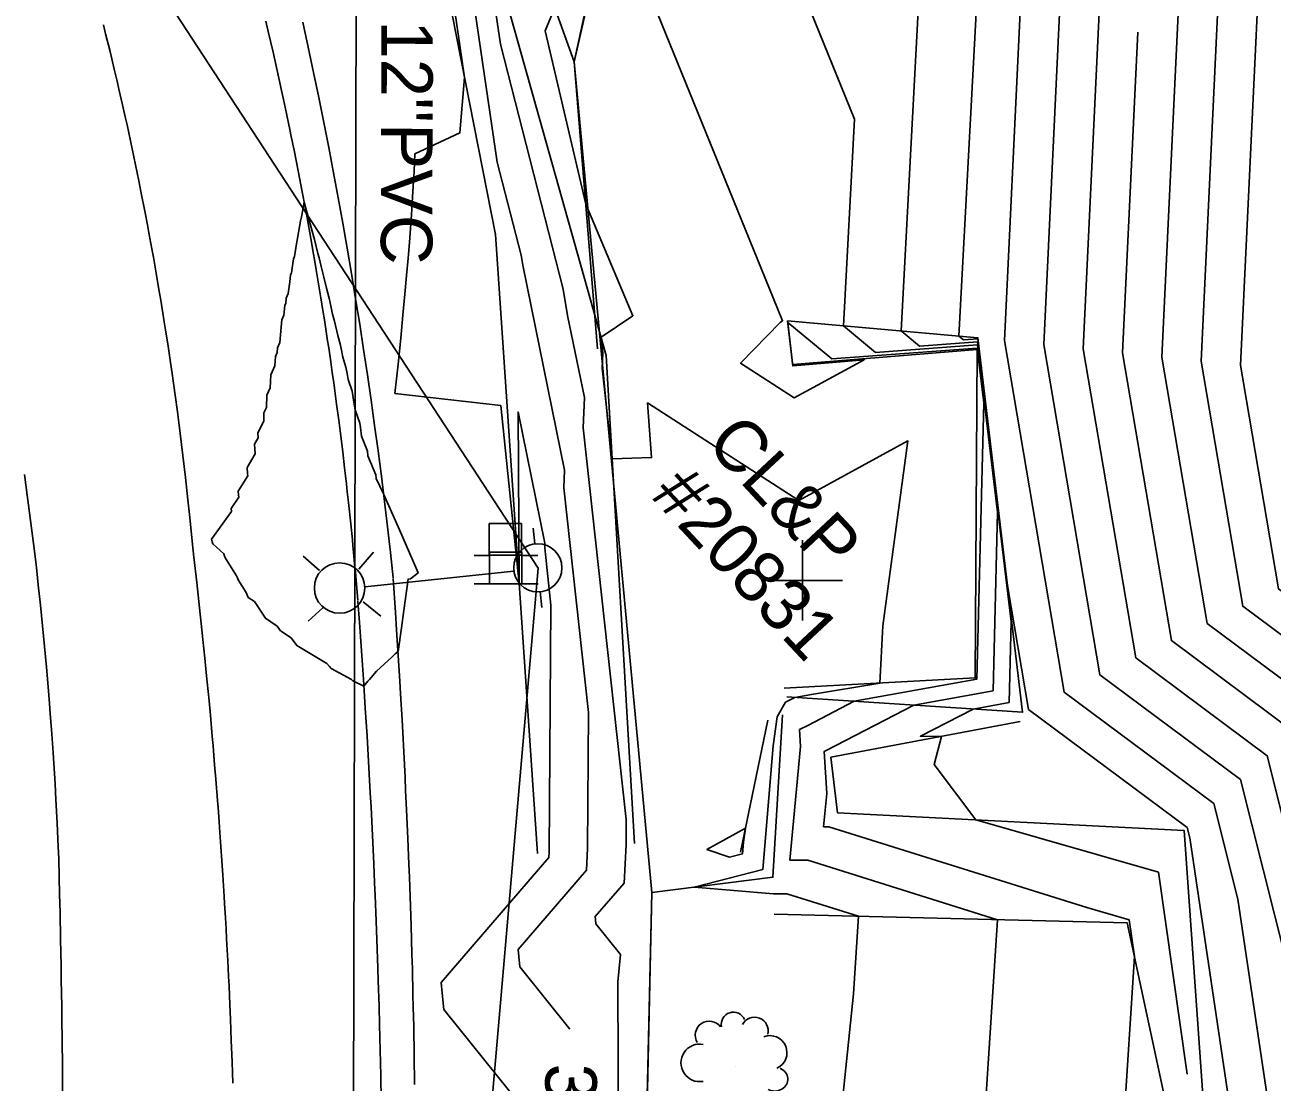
# Model space of a CAD drawing. Extents: x 487096 to 489566, y 221939 to 224454.
# Drawn here: x 488438.1 to 488515.7, y 223406.4 to 223472.1 of the extents above; entities that cross this region are included whole.
import ezdxf

# ---------------------------------------------------------------- set-up
doc = ezdxf.new("R2010")
doc.units = 0
for name, color, linetype in [('SV_BKLN_BKLN', 7, 'Continuous'), ('SV_BKLN_EARTH_TOE', 7, 'Continuous'), ('SV_BKLN_EARTH_TOP', 7, 'Continuous'), ('SV_PIPE_PLAS_12', 7, 'Continuous'), ('SV_PIPE_PLAS_TX', 7, 'Continuous'), ('SV_ROAD_BITRD', 7, 'Continuous'), ('SV_ROWL_HWYLOC', 7, 'Continuous'), ('SV_ROWL_STREET', 7, 'Continuous'), ('SV_SIGN_SIGN', 7, 'Continuous'), ('SV_SURF_INDEX_CONTOUR', 7, 'Continuous'), ('SV_SURF_INTER_CONTOUR', 7, 'Continuous'), ('SV_SURF_SPOT', 7, 'Continuous'), ('SV_TRAF_PVMTL', 7, 'Continuous'), ('SV_TREE_TREEVEG', 7, 'Continuous'), ('SV_UTOH_OVERHEAD_LINES', 7, 'Continuous'), ('SV_UTOH_UPOLT', 7, 'Continuous'), ('SV_UTOH_UTOH_TX', 7, 'Continuous'), ('SV_WALL_STONE_WALL', 7, 'Continuous')]:
    doc.layers.add(name, color=color, linetype=linetype)

msp = doc.modelspace()

# ---------------------------------------------------------------- linework, layer by layer
at = {"layer": 'SV_BKLN_BKLN'}
for points in [[(488485.31, 223430.866), (488497.188, 223431.512), (488497.312, 223451.947), (488485.84, 223451.008)], [(488484.292, 223428.887), (488482.589, 223420.665)]]:
    msp.add_lwpolyline(points, dxfattribs=at)
at = {"layer": 'SV_BKLN_EARTH_TOE'}
for points in [[(488469.961, 223420.582), (488467.339, 223459.105), (488461.972, 223486.415), (488459.949, 223502.528)], [(488484.686, 223416.811), (488506.643, 223416.262), (488512.539, 223388.8)]]:
    msp.add_lwpolyline(points, dxfattribs=at)
at = {"layer": 'SV_BKLN_EARTH_TOP'}
for points in [[(488474.03, 223609.885), (488463.275, 223570.978), (488459.199, 223552.217), (488465.983, 223535.806), (488467.423, 223503.001), (488467.747, 223474.673), (488474.24, 223451.573), (488476.004, 223421.2)], [(488512.539, 223388.8), (488510.187, 223422.021), (488488.627, 223423.114), (488488.217, 223426.57), (488499.994, 223428.804)]]:
    msp.add_lwpolyline(points, dxfattribs=at)
at = {"layer": 'SV_PIPE_PLAS_12'}
msp.add_line((488458.486, 223394.536), (488458.76, 223501.752), dxfattribs=at)
at = {"layer": 'SV_ROAD_BITRD'}
for points in [[(488460.986, 223437.739), (488460.813, 223439.322), (488460.632, 223440.905), (488460.444, 223442.487), (488460.247, 223444.068), (488460.042, 223445.648), (488459.83, 223447.227), (488459.609, 223448.804), (488459.381, 223450.381), (488459.145, 223451.957), (488458.901, 223453.531), (488458.648, 223455.104), (488458.388, 223456.676), (488458.12, 223458.246), (488457.845, 223459.815), (488457.561, 223461.383), (488457.27, 223462.949), (488456.97, 223464.514), (488456.663, 223466.077), (488456.348, 223467.638), (488456.025, 223469.198), (488455.694, 223470.757), (488455.356, 223472.313)], [(488462.314, 223406.214), (488462.289, 223408.014), (488462.257, 223409.813), (488462.233, 223411.013), (488462.214, 223411.813), (488462.174, 223413.413), (488462.149, 223414.313), (488462.095, 223416.112), (488462.034, 223417.912), (488461.99, 223419.112), (488461.959, 223419.912), (488461.893, 223421.511), (488461.814, 223423.311), (488461.758, 223424.511), (488461.72, 223425.311), (488461.639, 223426.91), (488461.575, 223428.11), (488461.531, 223428.91), (488461.441, 223430.51), (488461.394, 223431.309), (488461.297, 223432.909), (488461.196, 223434.509), (488461.126, 223435.575), (488460.982, 223437.708)]]:
    msp.add_lwpolyline(points, dxfattribs=at)
at = {"layer": 'SV_ROWL_HWYLOC'}
msp.add_lwpolyline([(487756.919, 223854.031), (487819.736, 223823.932), (487982.506, 223759.36), (488009.692, 223754.735), (488041.144, 223750.633), (488071.96, 223735.453), (488100.921, 223722.744), (488124.658, 223715.601), (488155.682, 223709.246), (488178.896, 223706.069), (488296.161, 223658.564), (488379.396, 223617.166), (488410.154, 223595.683), (488443.8, 223549.214), (488472.236, 223469.86), (488477.064, 223418.158), (488475.622, 223352.082), (488474.079, 223317.483), (488463.166, 223231.249), (488461.577, 223189.461)], dxfattribs=at)
at = {"layer": 'SV_ROWL_STREET'}
msp.add_lwpolyline([(488472.236, 223469.86), (488486.837, 223537.1), (488522.5, 223630.049)], dxfattribs=at)
at = {"layer": 'SV_SIGN_SIGN'}
for p, q in [((488466.01, 223439.134), (488466.983, 223439.134)), ((488468.958, 223439.134), (488469.985, 223439.134)), ((488466.024, 223437.356), (488466.997, 223437.356)), ((488468.972, 223437.356), (488469.999, 223437.356))]:
    msp.add_line(p, q, dxfattribs=at)
for points in [[(488466.961, 223439.144), (488468.964, 223439.144), (488468.964, 223441.112), (488466.961, 223441.112)], [(488466.975, 223437.366), (488468.978, 223437.366), (488468.978, 223439.334), (488466.975, 223439.334)]]:
    msp.add_lwpolyline(points, close=True, dxfattribs=at)
at = {"layer": 'SV_SURF_INDEX_CONTOUR'}
for points in [[(488471.978, 223409.661), (488468.866, 223413.538), (488468.801, 223414.177), (488468.756, 223414.608), (488473.005, 223419.543), (488473.075, 223420.9), (488473.14, 223429.366), (488471.601, 223443.342), (488471.648, 223444.432), (488469.044, 223457.198), (488468.941, 223457.815), (488467.456, 223463.599), (488465.035, 223480.187), (488467.467, 223492.224)], [(488493.689, 223473.812), (488492.585, 223453.104), (488493.729, 223452.157), (488497.341, 223452.428), (488499.43, 223435.03), (488499.301, 223429.979), (488497.061, 223429.573), (488493.781, 223427.879), (488495.083, 223427.872), (488494.643, 223426.125), (488497.238, 223422.677), (488508.584, 223419.416), (488510.375, 223406.859)], [(488524.879, 223390.272), (488522.508, 223406.244), (488517.007, 223428.162), (488509.392, 223433.834), (488506.342, 223451.738), (488507.297, 223471.696)]]:
    msp.add_lwpolyline(points, dxfattribs=at)
at = {"layer": 'SV_SURF_INTER_CONTOUR'}
for points in [[(488475.237, 223353.958), (488474.959, 223412.31), (488474.949, 223412.587), (488475.123, 223414.293), (488473.592, 223416.201), (488473.564, 223416.472), (488473.545, 223416.654), (488475.345, 223418.745), (488475.469, 223421.145), (488475.481, 223422.691), (488472.796, 223447.07), (488472.877, 223448.971), (488471.836, 223454.075), (488471.566, 223455.703), (488467.649, 223470.958), (488466.837, 223476.523), (488467.678, 223480.687), (488475.134, 223497.605), (488478.974, 223500.11), (488479.587, 223502.683), (488485.953, 223532.874)], [(488497.752, 223403.671), (488498.571, 223416.463), (488486.781, 223420.161), (488485.665, 223420.168), (488486.318, 223427.241), (488486.257, 223428.299), (488486.767, 223428.556), (488489.667, 223430.054), (488497.291, 223431.437), (488497.728, 223448.623), (488497.318, 223452.042), (488488.264, 223451.361), (488485.531, 223453.626), (488485.845, 223450.934), (488490.285, 223451.31), (488485.935, 223448.936), (488482.59, 223451.095), (488485.062, 223453.638), (488485.208, 223453.735), (488484.889, 223454.491), (488476.929, 223474.112), (488484.113, 223495.064), (488492.299, 223522.072)], [(488485.757, 223349.037), (488504.365, 223380.67), (488505.893, 223395.484), (488507.09, 223414.18), (488506.765, 223416.46), (488504.136, 223417.215), (488488.087, 223422.249), (488487.76, 223422.251), (488487.951, 223424.322), (488487.798, 223426.94), (488487.907, 223426.994), (488493.364, 223429.813), (488498.296, 223430.708), (488498.579, 223441.826), (488497.33, 223452.235), (488490.996, 223451.759), (488488.992, 223453.42), (488489.677, 223466.278), (488483.927, 223480.453), (488488.818, 223494.717), (488494.391, 223513.103)], [(488498.587, 223497.638), (488498.575, 223495.166), (488498.228, 223494.022), (488497.924, 223493.135), (488498.282, 223492.253), (488496.178, 223452.789), (488496.461, 223452.555), (488497.353, 223452.622), (488499.197, 223437.26), (488500.51, 223429.552), (488510.384, 223422.198), (488510.543, 223421.565), (488515.377, 223389.001), (488515.454, 223387.154), (488514.573, 223383.897), (488492.819, 223346.915)], [(488500.876, 223491.691), (488499.001, 223452.512), (488502.731, 223430.623), (488512.04, 223423.689), (488513.534, 223417.735), (488517.774, 223389.17), (488517.917, 223385.764), (488516.291, 223379.755), (488496.349, 223345.854), (488500.815, 223332.76), (488505.486, 223311.235), (488503.021, 223294.105), (488501.011, 223283.859), (488494.411, 223265.224), (488494.149, 223264.995), (488494.028, 223264.141), (488493.843, 223260.358), (488490.866, 223226.171), (488492.012, 223217.495)], [(488503.209, 223489.056), (488501.448, 223452.254), (488504.951, 223431.693), (488513.695, 223425.18), (488516.525, 223413.905), (488520.172, 223389.34), (488520.38, 223384.373), (488518.009, 223375.613), (488499.88, 223344.793), (488505.106, 223329.468), (488508.838, 223312.276), (488505.581, 223289.652), (488504.581, 223284.554), (488501.001, 223274.446), (488497.619, 223264.424), (488497.435, 223260.396), (488494.436, 223225.954), (488496.881, 223207.44)], [(488505.542, 223486.421), (488503.895, 223451.996), (488507.172, 223432.763), (488515.351, 223426.671), (488519.516, 223410.075), (488522.569, 223389.509), (488522.843, 223382.983), (488519.728, 223371.471), (488503.411, 223343.732), (488509.398, 223326.177), (488512.189, 223313.317), (488508.162, 223285.347), (488508.148, 223285.239), (488508.142, 223285.22), (488500.983, 223264.004), (488500.591, 223255.423), (488498.006, 223225.737), (488501.75, 223197.385)], [(488469.84, 223403.775), (488464.14, 223410.875), (488464.038, 223411.883), (488463.968, 223412.562), (488470.666, 223420.341), (488470.682, 223420.656), (488470.799, 223436.041), (488470.406, 223439.614), (488470.418, 223439.893), (488468.75, 223448.07), (488468.817, 223437.391), (488467.688, 223448.457), (488461.089, 223449.219), (488461.282, 223451.034), (488461.448, 223452.647), (488461.591, 223454.09), (488461.714, 223455.389), (488461.82, 223456.564), (488461.913, 223457.632), (488461.992, 223458.607), (488462.061, 223459.5), (488462.12, 223460.321), (488462.17, 223461.078), (488462.213, 223461.779), (488462.249, 223462.429), (488462.279, 223463.033), (488462.303, 223463.597), (488462.323, 223464.124), (488465.138, 223465.425), (488465.42, 223468.867), (488463.233, 223483.851)], [(488475.473, 223483.934), (488470.443, 223471.782), (488472.961, 223460.986), (488475.893, 223454.049), (488473.917, 223452.723), (488474.032, 223451.735), (488473.992, 223450.798), (488474.613, 223445.154), (488477.056, 223445.218), (488476.813, 223448.622), (488486.218, 223442.551), (488493.005, 223446.255), (488491.433, 223434.76), (488491.266, 223431.19), (488486.995, 223430.48), (488485.97, 223430.294), (488485.628, 223430.117), (488485.397, 223430.001), (488484.866, 223429.096), (488484.619, 223427.293), (488483.98, 223419.589), (488479.704, 223418.491), (488484.639, 223418.079), (488485.476, 223418.073), (488489.919, 223416.68), (488489.61, 223411.858), (488484.338, 223360.751)], [(488510.208, 223481.151), (488508.788, 223451.48), (488511.613, 223434.904), (488518.662, 223429.653), (488525.499, 223402.414), (488527.364, 223389.848), (488527.769, 223380.202), (488523.164, 223363.187), (488510.473, 223341.61), (488517.981, 223319.594), (488518.891, 223315.4), (488517.578, 223306.276), (488514.66, 223284.348), (488513.561, 223280.499), (488507.71, 223263.162), (488506.903, 223245.477), (488505.146, 223225.303), (488509.668, 223191.06)], [(488512.541, 223478.516), (488511.235, 223451.223), (488513.833, 223435.974), (488520.318, 223431.144), (488528.49, 223398.584), (488529.762, 223390.017), (488530.232, 223378.811), (488524.883, 223359.045), (488514.003, 223340.55), (488522.204, 223316.501), (488522.235, 223316.395), (488522.222, 223316.267), (488517.916, 223283.903), (488516.27, 223278.139), (488511.074, 223262.742), (488510.059, 223240.504), (488508.716, 223225.086), (488512.172, 223198.915)], [(488514.676, 223206.771), (488512.286, 223224.869), (488513.215, 223235.531), (488514.438, 223262.321), (488518.979, 223275.778), (488521.172, 223283.458), (488524.952, 223311.868), (488525.38, 223316.004), (488524.369, 223319.447), (488517.534, 223339.489), (488526.601, 223354.903), (488532.695, 223377.421), (488532.16, 223390.187), (488531.482, 223394.754), (488521.974, 223432.635), (488516.054, 223437.045), (488513.682, 223450.965), (488514.874, 223475.881)]]:
    msp.add_lwpolyline(points, dxfattribs=at)
for points in [[(488462.052, 223437.683), (488462.527, 223438.048), (488461.992, 223439.294), (488461.368, 223440.729), (488460.633, 223442.403), (488460.385, 223442.962), (488459.927, 223443.92), (488459.919, 223443.995), (488459.908, 223444.095), (488459.902, 223444.145), (488459.415, 223445.327), (488459.377, 223445.626), (488459.019, 223446.554), (488458.944, 223447.091), (488458.902, 223447.364), (488458.616, 223448.19), (488458.538, 223448.676), (488458.421, 223449.346), (488458.185, 223450.086), (488458.116, 223450.463), (488458.043, 223450.849), (488457.851, 223451.465), (488457.743, 223452.019), (488457.685, 223452.305), (488457.529, 223452.816), (488457.341, 223453.723), (488457.214, 223454.142), (488457.123, 223454.563), (488456.994, 223455.144), (488456.926, 223455.445), (488456.827, 223455.775), (488456.668, 223456.461), (488456.572, 223456.864), (488456.498, 223457.11), (488456.368, 223457.648), (488456.3, 223457.926), (488456.079, 223458.796), (488456.036, 223458.938), (488455.72, 223460.138), (488455.701, 223460.199), (488455.536, 223460.808), (488455.449, 223461.117), (488455.386, 223460.787), (488455.378, 223460.765), (488455.25, 223460.076), (488455.241, 223460.053), (488455.019, 223458.755), (488454.98, 223458.656), (488454.836, 223457.734), (488454.78, 223457.594), (488454.734, 223457.293), (488454.652, 223456.711), (488454.604, 223456.592), (488454.546, 223456.165), (488454.459, 223455.44), (488454.335, 223455.14), (488454.297, 223454.823), (488454.244, 223454.695), (488454.176, 223454.08), (488454.055, 223453.791), (488454.009, 223453.344), (488453.93, 223452.39), (488453.783, 223452.059), (488453.761, 223451.756), (488453.652, 223451.511), (488453.617, 223450.926), (488453.368, 223450.378), (488453.346, 223449.963), (488453.332, 223449.559), (488453.112, 223449.099), (488453.099, 223448.342), (488452.935, 223448.017), (488452.941, 223447.483), (488452.564, 223446.772), (488452.573, 223446.449), (488452.358, 223446.053), (488452.391, 223445.45), (488451.894, 223444.601), (488451.929, 223444.211), (488451.943, 223444.082), (488451.335, 223443.124), (488451.363, 223442.913), (488451.387, 223442.754), (488450.899, 223442.049), (488450.931, 223441.875), (488449.69, 223440.149), (488449.731, 223439.989), (488449.77, 223439.865), (488450.449, 223439.223), (488450.47, 223439.162), (488450.516, 223439.035), (488451.245, 223437.865), (488451.292, 223437.742), (488451.343, 223437.616), (488451.834, 223436.818), (488451.962, 223436.524), (488452.35, 223436.276), (488453.03, 223435.227), (488453.77, 223434.721), (488453.975, 223434.432), (488454.626, 223434.004), (488454.986, 223433.527), (488456.846, 223432.406), (488457.014, 223432.212), (488457.114, 223432.097), (488458.397, 223431.413), (488458.473, 223431.334), (488459.159, 223431.006), (488459.408, 223431.316), (488459.501, 223431.407), (488459.948, 223431.932), (488460.899, 223432.802), (488461.098, 223433.008), (488461.282, 223433.151), (488461.491, 223434.633), (488461.643, 223435.71), (488461.914, 223437.663)], [(488481.907, 223420.355), (488482.72, 223420.564), (488482.78, 223421.287), (488482.899, 223422.162), (488480.503, 223420.834)]]:
    msp.add_lwpolyline(points, close=True, dxfattribs=at)
at = {"layer": 'SV_SURF_SPOT'}
for p, q in [((488486.439, 223435.077), (488486.439, 223440.079)), ((488483.938, 223437.578), (488488.94, 223437.578)), ((488486.439, 223437.578), (488486.439, 223437.578))]:
    msp.add_line(p, q, dxfattribs=at)
at = {"layer": 'SV_TRAF_PVMTL'}
for points in [[(488458.782, 223436.332), (488458.718, 223437.086), (488458.63, 223438.09), (488458.584, 223438.592), (488458.538, 223439.093), (488458.474, 223439.76), (488458.441, 223440.094), (488458.341, 223441.094), (488458.201, 223442.425), (488458.129, 223443.089), (488458.073, 223443.587), (488457.998, 223444.251), (488457.959, 223444.582), (488457.841, 223445.576), (488457.678, 223446.898), (488457.593, 223447.558), (488457.463, 223448.548), (488457.284, 223449.865), (488457.192, 223450.522), (488457.098, 223451.179), (488456.97, 223452.054), (488456.904, 223452.491), (488456.704, 223453.801), (488456.613, 223454.382), (488456.489, 223455.157), (488456.426, 223455.544), (488456.283, 223456.413), (488456.201, 223456.902), (488456.09, 223457.553), (488456.034, 223457.879), (488455.863, 223458.854), (488455.628, 223460.152), (488455.509, 223460.801), (488455.326, 223461.772), (488455.076, 223463.065), (488454.949, 223463.711), (488454.819, 223464.356), (488454.644, 223465.215), (488454.556, 223465.645), (488454.285, 223466.931), (488454.163, 223467.502), (488453.997, 223468.263), (488453.914, 223468.643), (488453.723, 223469.497), (488453.506, 223470.457), (488453.209, 223471.735), (488453.059, 223472.373)], [(488448.499, 223439.831), (488448.315, 223441.677), (488448.218, 223442.597), (488448.066, 223443.974), (488447.905, 223445.346), (488447.822, 223446.031), (488447.649, 223447.398), (488447.56, 223448.08), (488447.422, 223449.102), (488447.231, 223450.46), (488447.132, 223451.138), (488446.98, 223452.154), (488446.824, 223453.167), (488446.744, 223453.673), (488446.525, 223455.02), (488446.413, 223455.692), (488446.24, 223456.699), (488446.063, 223457.704), (488445.973, 223458.206), (488445.789, 223459.208), (488445.695, 223459.709), (488445.552, 223460.459), (488445.292, 223461.79), (488445.158, 223462.454), (488444.954, 223463.449), (488444.746, 223464.443), (488444.64, 223464.939), (488444.424, 223465.931), (488444.315, 223466.426), (488444.148, 223467.168), (488443.922, 223468.156), (488443.807, 223468.649), (488443.633, 223469.389), (488443.366, 223470.497), (488443.093, 223471.603), (488442.955, 223472.156)], [(488438.046, 223444.164), (488438.22, 223442.894), (488438.305, 223442.258), (488438.428, 223441.303), (488438.548, 223440.347), (488438.607, 223439.869), (488438.742, 223438.734), (488438.807, 223438.166), (488438.903, 223437.313), (488439.041, 223436.033), (488439.172, 223434.75), (488439.235, 223434.109), (488439.355, 223432.823), (488439.413, 223432.18), (488439.497, 223431.214), (488439.603, 223429.925), (488439.653, 223429.279), (488439.725, 223428.31), (488439.826, 223426.854), (488439.908, 223425.558), (488439.947, 223424.909), (488440.002, 223423.935), (488440.077, 223422.472), (488440.143, 223421.006), (488440.173, 223420.272)], [(488451.004, 223406.294), (488450.983, 223406.958), (488450.961, 223407.622), (488450.929, 223408.507), (488450.913, 223408.95), (488450.86, 223410.277), (488450.823, 223411.162), (488450.769, 223412.342), (488450.741, 223412.932), (488450.692, 223413.928), (488450.622, 223415.256), (488450.585, 223415.919), (488450.547, 223416.583), (488450.495, 223417.468), (488450.468, 223417.91), (488450.384, 223419.238), (488450.325, 223420.123), (488450.244, 223421.303), (488450.202, 223421.893), (488450.154, 223422.556), (488450.088, 223423.441), (488450.054, 223423.883), (488449.949, 223425.211), (488449.877, 223426.095), (488449.778, 223427.275), (488449.726, 223427.865), (488449.608, 223429.192), (488449.527, 223430.077), (488449.415, 223431.256), (488449.358, 223431.846), (488449.27, 223432.731), (488449.151, 223433.91), (488449.089, 223434.5), (488448.9, 223436.269), (488448.77, 223437.448), (488448.59, 223439.021), (488448.498, 223439.807)], [(488460.239, 223405.194), (488460.208, 223406.766), (488460.191, 223407.552), (488460.154, 223409.124), (488460.134, 223409.911), (488460.101, 223411.09), (488460.054, 223412.662), (488460.028, 223413.448), (488459.988, 223414.627), (488459.923, 223416.395), (488459.861, 223417.967), (488459.828, 223418.753), (488459.776, 223419.932), (488459.693, 223421.7), (488459.605, 223423.469), (488459.558, 223424.353), (488459.472, 223425.925), (488459.427, 223426.711), (488459.357, 223427.89), (488459.247, 223429.658), (488459.131, 223431.426), (488459.071, 223432.31), (488458.946, 223434.079), (488458.881, 223434.963), (488458.78, 223436.289)], [(488440.175, 223420.258), (488440.231, 223418.029), (488440.257, 223416.915), (488440.292, 223415.244), (488440.323, 223413.572), (488440.337, 223412.737), (488440.362, 223411.066), (488440.373, 223410.231), (488440.387, 223408.978), (488440.402, 223407.307), (488440.408, 223406.472), (488440.416, 223405.219)]]:
    msp.add_lwpolyline(points, dxfattribs=at)
at = {"layer": 'SV_TREE_TREEVEG'}
msp.add_line((488482.256, 223407.309), (488482.256, 223407.309), dxfattribs=at)
for centre, radius, start, end in [((488480.645, 223409.272), 0.874, 35.99331, 211.459), ((488482.145, 223409.96), 0.75, 23.2911, 192.35792), ((488483.46, 223409.546), 0.85, 345.53076, 152.70931), ((488480.056, 223407.555), 1.171, 79.3292, 279.98885), ((488484.421, 223408.19), 1.059, 294.18586, 111.10825)]:
    msp.add_arc(centre, radius, start, end, dxfattribs=at)
msp.add_ellipse((488484.711, 223406.542), major_axis=(0.822, -0.013), ratio=0.901056, start_param=4.216583, end_param=7.444153, dxfattribs=at)
at = {"layer": 'SV_UTOH_OVERHEAD_LINES'}
msp.add_lwpolyline([(488477.012, 222631.438), (488424.125, 222778.25), (488391.68, 223012.955), (488449.873, 223205.72), (488469.995, 223438.334), (488349.561, 223622.886), (488159.178, 223693.118), (487993.175, 223755.783), (487804.196, 223830.216), (487742.262, 223860.212)], dxfattribs=at)
at = {"layer": 'SV_UTOH_UPOLT'}
for p, q in [((488469.694, 223440.839), (488469.801, 223439.846)), ((488456.394, 223438.205), (488455.388, 223439.095)), ((488458.837, 223438.286), (488459.765, 223439.34)), ((488468.484, 223438.162), (488459.216, 223437.179)), ((488470.132, 223436.891), (488470.239, 223435.896)), ((488456.599, 223435.865), (488455.69, 223435.041)), ((488459.121, 223436.245), (488460.223, 223435.356))]:
    msp.add_line(p, q, dxfattribs=at)
for centre, radius in [((488469.978, 223438.362), 1.5), ((488457.648, 223437.103), 1.57)]:
    msp.add_circle(centre, radius, dxfattribs=at)
at = {"layer": 'SV_WALL_STONE_WALL'}
for points in [[(488478.135, 223495.505), (488472.236, 223469.86), (488473.697, 223451.995)], [(488485.475, 223430.326), (488500.138, 223429.373), (488497.357, 223452.685), (488485.519, 223453.725), (488485.847, 223450.908)], [(488485.21, 223429.222), (488484.6, 223419.11), (488477.064, 223418.158), (488475.622, 223352.082), (488474.079, 223317.483)]]:
    msp.add_lwpolyline(points, dxfattribs=at)

# ---------------------------------------------------------------- texts
at = {"layer": 'SV_PIPE_PLAS_TX'}
msp.add_text("12''PVC", height=3.2, rotation=269.85329, dxfattribs=at).set_placement((488460.25, 223472.432))
at = {"layer": 'SV_SURF_INDEX_CONTOUR'}
msp.add_text('355', height=3.2, rotation=270.59512, dxfattribs=at).set_placement((488470.437, 223407.496))
at = {"layer": 'SV_UTOH_UTOH_TX'}
for s, p in [('CL&P', (488480.356, 223446.02)), ('#20831', (488476.921, 223442.812))]:
    msp.add_text(s, height=3.2, rotation=313.03859, dxfattribs=at).set_placement(p)

doc.saveas('drawing.dxf')
